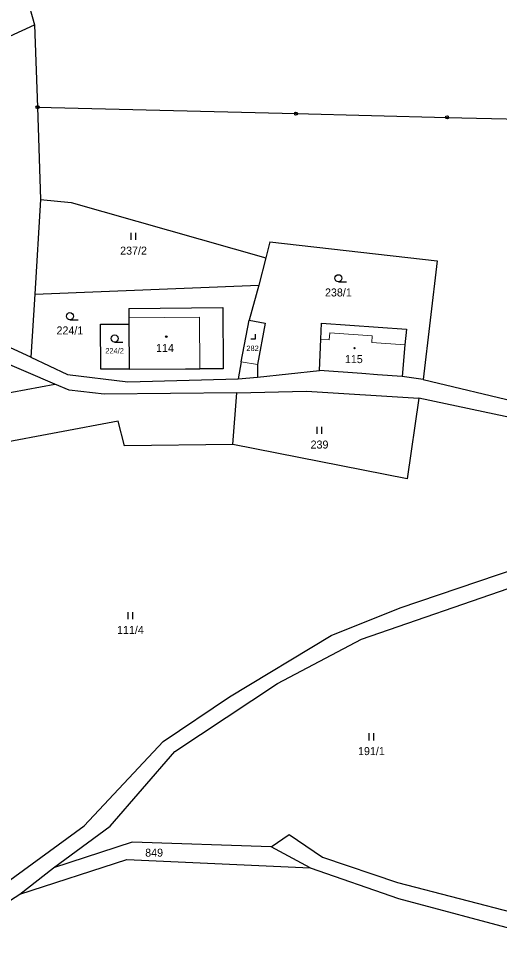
# Model space of a CAD drawing. Extents: x -739410 to -735662, y -942282 to -940043.
# Drawn here: x -737454.1 to -737352, y -941019.2 to -940819.5 of the extents above; entities that cross this region are included whole.
import ezdxf
from ezdxf.enums import TextEntityAlignment as Align

# ---------------------------------------------------------------- set-up
doc = ezdxf.new("R2010")
doc.units = 0
doc.header["$LTSCALE"] = 0.68
for name, color, linetype, lineweight in [('1', 7, 'Continuous', 25), ('3', 7, 'Continuous', 25), ('4', 7, 'Continuous', 13), ('5', 7, 'Continuous', 25), ('8', 7, 'Continuous', 25)]:
    doc.layers.add(name, color=color, linetype=linetype, lineweight=lineweight)
doc.layers.add('2', color=7, linetype='Continuous')

msp = doc.modelspace()

# ---------------------------------------------------------------- linework, layer by layer
at = {"layer": '1'}
for p, q in [((-737458.33, -940793.46), (-737450.75, -940820.84)), ((-737471.4, -940830.22), (-737450.75, -940820.84)), ((-737450.75, -940820.84), (-737450.1, -940838.3)), ((-737450.1, -940838.3), (-737395.2, -940839.67)), ((-737450.1, -940838.3), (-737449.45, -940857.88)), ((-737395.2, -940839.67), (-737363.1, -940840.47)), ((-737363.1, -940840.47), (-737332.73, -940841.22)), ((-737449.45, -940857.88), (-737450.69, -940877.98)), ((-737449.45, -940857.88), (-737442.99, -940858.51)), ((-737442.99, -940858.51), (-737401.62, -940870.28)), ((-737400.76, -940866.88), (-737401.62, -940870.28)), ((-737400.76, -940866.88), (-737365.19, -940870.9)), ((-737401.62, -940870.28), (-737403.09, -940876.08)), ((-737365.19, -940870.9), (-737368.17, -940896.08)), ((-737450.69, -940877.98), (-737403.09, -940876.08)), ((-737403.09, -940876.08), (-737405.12, -940883.55)), ((-737450.69, -940877.98), (-737451.52, -940891.34)), ((-737430.71, -940881.05), (-737410.74, -940880.84)), ((-737430.71, -940881.05), (-737430.7, -940883.05)), ((-737410.74, -940880.84), (-737410.66, -940893.86)), ((-737430.7, -940883.05), (-737430.69, -940884.4)), ((-737436.65, -940893.9), (-737436.72, -940884.38)), ((-737436.72, -940884.38), (-737430.69, -940884.4)), ((-737430.69, -940884.4), (-737430.63, -940893.91)), ((-737406.82, -940892.34), (-737405.12, -940883.55)), ((-737405.12, -940883.55), (-737401.73, -940884.17)), ((-737401.73, -940884.17), (-737403.38, -940892.95)), ((-737389.89, -940887.58), (-737389.74, -940884.16)), ((-737389.74, -940884.16), (-737371.74, -940885.45)), ((-737451.52, -940891.34), (-737461.21, -940886.94)), ((-737371.74, -940885.45), (-737372.07, -940888.73)), ((-737390.21, -940894.22), (-737389.89, -940887.58)), ((-737372.07, -940888.73), (-737372.66, -940895.46)), ((-737451.52, -940891.34), (-737443.71, -940895.03)), ((-737446.45, -940897.08), (-737459.33, -940891.54)), ((-737406.82, -940892.34), (-737407.45, -940896)), ((-737403.38, -940892.95), (-737403.35, -940895.63)), ((-737443.71, -940895.03), (-737430.91, -940896.58)), ((-737430.63, -940893.91), (-737436.65, -940893.9)), ((-737430.63, -940893.91), (-737418.68, -940893.86)), ((-737418.68, -940893.86), (-737415.66, -940893.86)), ((-737410.66, -940893.86), (-737415.66, -940893.86)), ((-737403.35, -940895.63), (-737390.21, -940894.22)), ((-737381.23, -940894.83), (-737390.21, -940894.22)), ((-737377.89, -940895.11), (-737381.23, -940894.83)), ((-737372.66, -940895.46), (-737377.89, -940895.11)), ((-737480.23, -940903.41), (-737446.45, -940897.08)), ((-737443.37, -940898.4), (-737446.45, -940897.08)), ((-737430.91, -940896.58), (-737407.45, -940896)), ((-737407.45, -940896), (-737403.35, -940895.63)), ((-737368.17, -940896.08), (-737372.66, -940895.46)), ((-737368.17, -940896.08), (-737342.58, -940902.27)), ((-737435.96, -940899.24), (-737443.37, -940898.4)), ((-737407.75, -940898.91), (-737435.96, -940899.24)), ((-737408.62, -940909.88), (-737407.75, -940898.91)), ((-737407.75, -940898.91), (-737392.99, -940898.58)), ((-737392.99, -940898.58), (-737369.12, -940900.1)), ((-737369.12, -940900.1), (-737371.6, -940917.22)), ((-737343.19, -940905.57), (-737369.12, -940900.1)), ((-737432.99, -940904.99), (-737459.26, -940909.87)), ((-737431.63, -940910.2), (-737432.99, -940904.99)), ((-737408.62, -940909.88), (-737431.63, -940910.2)), ((-737371.6, -940917.22), (-737408.62, -940909.88)), ((-737373.06, -940944.61), (-737348.21, -940936.15)), ((-737381.31, -940951.22), (-737348.05, -940939.78)), ((-737387.72, -940950.48), (-737373.06, -940944.61)), ((-737409.31, -940963.5), (-737387.72, -940950.48)), ((-737399.11, -940960.67), (-737381.31, -940951.22)), ((-737420.93, -940975.11), (-737399.11, -940960.67)), ((-737423.42, -940972.94), (-737409.31, -940963.5)), ((-737440.23, -940990.85), (-737423.42, -940972.94)), ((-737434.69, -940990.96), (-737420.93, -940975.11)), ((-737464.65, -941008.66), (-737440.23, -940990.85)), ((-737446.74, -940999.76), (-737434.69, -940990.96)), ((-737400.45, -940995.3), (-737396.65, -940992.7)), ((-737396.65, -940992.7), (-737389.58, -940997.55)), ((-737429.97, -940994.32), (-737446.74, -940999.76)), ((-737400.45, -940995.3), (-737429.97, -940994.32)), ((-737392.2, -940999.75), (-737400.45, -940995.3)), ((-737453.9, -941005.4), (-737431.16, -940998.02)), ((-737431.16, -940998.02), (-737392.2, -940999.75)), ((-737389.58, -940997.55), (-737373.62, -941002.87)), ((-737453.9, -941005.4), (-737446.74, -940999.76)), ((-737392.2, -940999.75), (-737373.39, -941006.26)), ((-737373.62, -941002.87), (-737339.84, -941011.68)), ((-737465.37, -941012.63), (-737453.9, -941005.4)), ((-737373.39, -941006.26), (-737325.52, -941019.18))]:
    msp.add_line(p, q, dxfattribs=at)
at = {"layer": '3'}
for p, q in [((-737430.221, -940866.48), (-737430.221, -940864.98)), ((-737429.22, -940866.48), (-737429.22, -940864.98)), ((-737386.183, -940875.36), (-737384.433, -940875.36)), ((-737443.223, -940883.42), (-737441.473, -940883.42)), ((-737433.723, -940888.16), (-737431.973, -940888.16)), ((-737390.711, -940907.65), (-737390.711, -940906.15)), ((-737389.71, -940907.65), (-737389.71, -940906.15)), ((-737430.881, -940947.01), (-737430.881, -940945.51)), ((-737429.88, -940947.01), (-737429.88, -940945.51)), ((-737379.681, -940972.73), (-737379.681, -940971.23)), ((-737378.68, -940972.73), (-737378.68, -940971.23))]:
    msp.add_line(p, q, dxfattribs=at)
msp.add_lwpolyline([(-737404.771, -940887.49), (-737403.77, -940887.49), (-737403.77, -940886.49)], dxfattribs=at)
for centre in [(-737386.1829, -940874.6098), (-737443.2229, -940882.6698), (-737433.7229, -940887.4098)]:
    msp.add_circle(centre, 0.75, dxfattribs=at)
at = {"layer": '4'}
for p, q in [((-737430.7, -940883.05), (-737415.73, -940882.9)), ((-737415.73, -940882.9), (-737415.66, -940893.86)), ((-737388.12, -940887.7), (-737388.02, -940886.23)), ((-737388.02, -940886.23), (-737378.98, -940886.84)), ((-737378.98, -940886.84), (-737379.07, -940888.25)), ((-737389.89, -940887.58), (-737388.12, -940887.7)), ((-737379.07, -940888.25), (-737372.07, -940888.73)), ((-737403.38, -940892.95), (-737406.82, -940892.34))]:
    msp.add_line(p, q, dxfattribs=at)
at = {"layer": '5'}
for centre, radius in [((-737422.7468, -940887.0092), 0.175), ((-737382.7846, -940889.4594), 0.1172)]:
    msp.add_circle(centre, radius, dxfattribs=at)
at = {"layer": '8'}
for centre, radius in [((-737450.1, -940838.2999), 0.335), ((-737450.1, -940838.2999), 0.0203), ((-737395.2, -940839.6699), 0.335), ((-737395.2, -940839.6699), 0.0203), ((-737363.1, -940840.4699), 0.335), ((-737363.1, -940840.4699), 0.0203)]:
    msp.add_circle(centre, radius, dxfattribs=at)

# ---------------------------------------------------------------- texts
at = {"layer": '2'}
for s, height, p in [('237/2', 1.7, (-737429.71, -940869.605)), ('238/1', 1.7, (-737386.19, -940878.485)), ('224/1', 1.7, (-737443.23, -940886.545)), ('114', 1.7, (-737423.029, -940890.275)), ('282', 1.14, (-737404.42, -940890.065)), ('224/2', 1.14, (-737433.729, -940890.585)), ('115', 1.7, (-737382.909, -940892.635)), ('239', 1.7, (-737390.199, -940910.775)), ('111/4', 1.7, (-737430.37, -940950.135)), ('191/1', 1.7, (-737379.17, -940975.855)), ('849', 1.7, (-737425.339, -940997.415))]:
    msp.add_text(s, height=height, dxfattribs=at).set_placement(p, align=Align.CENTER)

doc.saveas('drawing.dxf')
